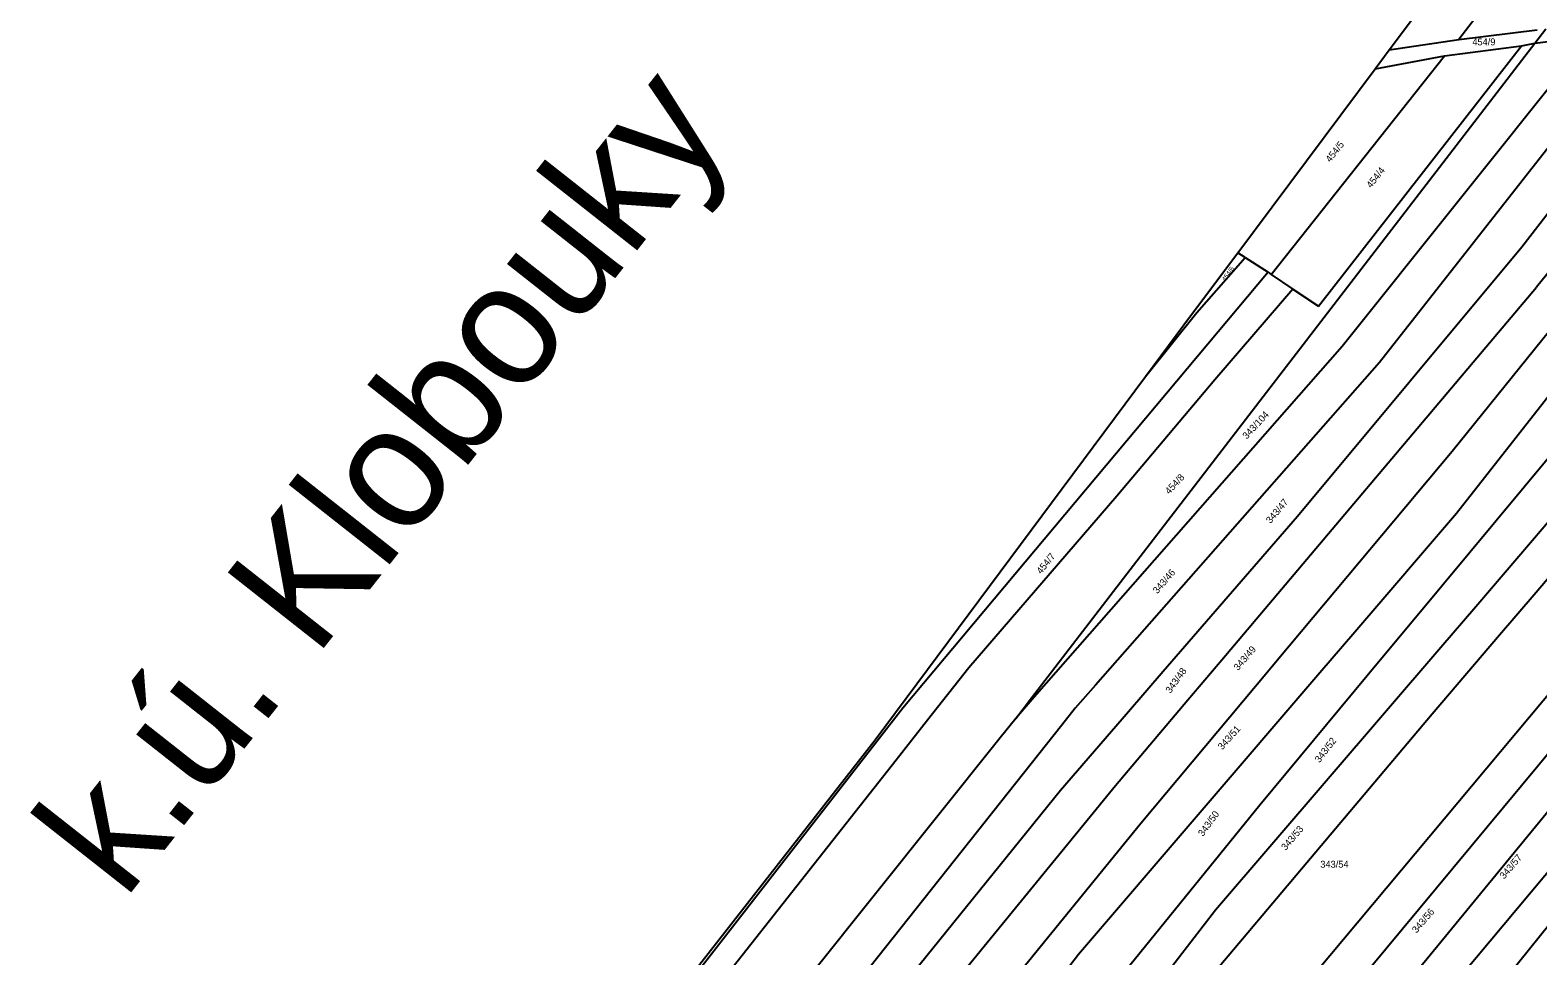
# Model space of a CAD drawing. Extents: x -580630 to -576196, y -1189024 to -1183567.
# Drawn here: x -580495.5 to -580125.3, y -1185848.6 to -1185621.3 of the extents above; entities that cross this region are included whole.
import ezdxf

# ---------------------------------------------------------------- set-up
doc = ezdxf.new("R2010")
doc.units = 0
for name, color, linetype in [('Vrstva 1', 7, 'Continuous'), ('Vrstva 13', 7, 'Continuous'), ('Vrstva 18', 7, 'Continuous'), ('Vrstva 6', 7, 'Continuous'), ('Vrstva 61', 7, 'Continuous')]:
    doc.layers.add(name, color=color, linetype=linetype)

msp = doc.modelspace()

# ---------------------------------------------------------------- linework, layer by layer
at = {"layer": 'Vrstva 1'}
for p, q in [((-580126.09, -1185624.48), (-580123.34, -1185620.94)), ((-580249.66, -1185785.26), (-580126.09, -1185624.48)), ((-580189.56, -1185894.3), (-580077.82, -1185758.25)), ((-580253.54, -1185790.3), (-580249.66, -1185785.26)), ((-580253.54, -1185790.3), (-580257.35, -1185795.07)), ((-580257.35, -1185795.07), (-580303.59, -1185852.97))]:
    msp.add_line(p, q, dxfattribs=at)
at = {"layer": 'Vrstva 13'}
for p, q in [((-580161.82, -1185626.13), (-580139.93, -1185596.8)), ((-580165.31, -1185630.8), (-580161.82, -1185626.13)), ((-580199, -1185675.94), (-580165.31, -1185630.8)), ((-580210.35, -1185691.15), (-580199, -1185675.94)), ((-580221.65, -1185706.34), (-580210.35, -1185691.15)), ((-580288.01, -1185795.54), (-580221.65, -1185706.34)), ((-580358.28, -1185885.39), (-580288.01, -1185795.54))]:
    msp.add_line(p, q, dxfattribs=at)
at = {"layer": 'Vrstva 6'}
for p, q in [((-580040.48, -1185487.18), (-580144.73, -1185623.59)), ((-580044.77, -1185611.67), (-580145.31, -1185740)), ((-580057.93, -1185615), (-580146.37, -1185724.78)), ((-580071.89, -1185617.85), (-580125.68, -1185684.41)), ((-580100.26, -1185621.38), (-580164.23, -1185702.87)), ((-580144.73, -1185623.59), (-580125.5, -1185621.21)), ((-580087, -1185619.79), (-580129.27, -1185674.58)), ((-580179.16, -1185689.04), (-580129.37, -1185625.12)), ((-580112.59, -1185622.86), (-580173.41, -1185698.95)), ((-580161.82, -1185626.13), (-580144.73, -1185623.59)), ((-580148.25, -1185627.63), (-580129.37, -1185625.12)), ((-580129.37, -1185625.12), (-580126.09, -1185624.48)), ((-580126.09, -1185624.48), (-580112.59, -1185622.86)), ((-580190.78, -1185681.29), (-580148.25, -1185627.63)), ((-580165.31, -1185630.8), (-580148.25, -1185627.63)), ((-580209.02, -1185690.65), (-580197.19, -1185677.1)), ((-580197.19, -1185677.1), (-580199, -1185675.94)), ((-580197.19, -1185677.1), (-580191.58, -1185680.71)), ((-580129.27, -1185674.58), (-580184.31, -1185740.71)), ((-580191.58, -1185680.71), (-580281.28, -1185787.81)), ((-580191.58, -1185680.71), (-580190.78, -1185681.29)), ((-580202.96, -1185775.93), (-580125.68, -1185684.41)), ((-580190.78, -1185681.29), (-580185.51, -1185684.93)), ((-580185.51, -1185684.93), (-580204.64, -1185707.18)), ((-580185.51, -1185684.93), (-580179.16, -1185689.04)), ((-580221.65, -1185706.34), (-580209.02, -1185690.65)), ((-580173.41, -1185698.95), (-580249, -1185785.12)), ((-580164.23, -1185702.87), (-580233.94, -1185782.12)), ((-580204.64, -1185707.18), (-580228.67, -1185735.7)), ((-580017.59, -1185710.64), (-580171.19, -1185901.31)), ((-580146.37, -1185724.78), (-580186.35, -1185772.54)), ((-580121.78, -1185725.25), (-580155.77, -1185766.1)), ((-580228.67, -1185735.7), (-580265.04, -1185777.88)), ((-580117.05, -1185735.44), (-580140.59, -1185762.9)), ((-580103.91, -1185733.76), (-580126.26, -1185759.95)), ((-580145.31, -1185740), (-580170.3, -1185769.16)), ((-580184.31, -1185740.71), (-580217.29, -1185778.79)), ((-580174.56, -1185861.14), (-580083.2, -1185751.18)), ((-580059.05, -1185751.68), (-580178.06, -1185893.99)), ((-580126.26, -1185759.95), (-580134.71, -1185769.84)), ((-580211.03, -1185889.9), (-580105.71, -1185763.93)), ((-580155.77, -1185766.1), (-580164.02, -1185776.02)), ((-580140.59, -1185762.9), (-580149.15, -1185772.88)), ((-580170.3, -1185769.16), (-580178.85, -1185779.14)), ((-580134.71, -1185769.84), (-580151.3, -1185789.28)), ((-580149.15, -1185772.88), (-580204.46, -1185837.4)), ((-580186.35, -1185772.54), (-580194.62, -1185782.43)), ((-580211.25, -1185785.75), (-580202.96, -1185775.93)), ((-580164.02, -1185776.02), (-580193.62, -1185811.58)), ((-580265.04, -1185777.88), (-580275.16, -1185790.71)), ((-580178.85, -1185779.14), (-580238.08, -1185848.26)), ((-580217.29, -1185778.79), (-580225.83, -1185788.66)), ((-580233.94, -1185782.12), (-580238.93, -1185787.79)), ((-580194.62, -1185782.43), (-580222.8, -1185816.09)), ((-580281.28, -1185787.81), (-580331.12, -1185851.88)), ((-580249, -1185785.12), (-580253.54, -1185790.3)), ((-580238.93, -1185787.79), (-580242.21, -1185791.93)), ((-580229.01, -1185806.78), (-580211.25, -1185785.75)), ((-580242.21, -1185791.93), (-580289.28, -1185851.33)), ((-580275.16, -1185790.71), (-580282.92, -1185800.56)), ((-580225.83, -1185788.66), (-580242.55, -1185807.97)), ((-580151.3, -1185789.28), (-580210.5, -1185859.48)), ((-580282.92, -1185800.56), (-580332.16, -1185863.02)), ((-580265.99, -1185852.06), (-580229.01, -1185806.78)), ((-580242.55, -1185807.97), (-580288.58, -1185864.9)), ((-580193.62, -1185811.58), (-580260.15, -1185893.74)), ((-580222.8, -1185816.09), (-580261.85, -1185863.97)), ((-580204.46, -1185837.4), (-580250.59, -1185897.1)), ((-580238.08, -1185848.26), (-580268.02, -1185887.2))]:
    msp.add_line(p, q, dxfattribs=at)

# ---------------------------------------------------------------- texts
at = {"layer": 'Vrstva 18'}
for s, p in [('454/9', (-580141.42, -1185625.03)), ('343/54', (-580178.743, -1185826.97))]:
    msp.add_text(s, height=1.7, dxfattribs=at).set_placement(p)
for s, height, rotation, p in [('454/5', 1.7, 51.5662, (-580176.302, -1185653.883)), ('454/4', 1.7, 51.5662, (-580166.273, -1185660.226)), ('454/6', 1.14, 54.83206, (-580202.084, -1185683.068)), ('343/104', 1.7, 47.15443, (-580196.802, -1185721.86)), ('454/8', 1.7, 47.15443, (-580215.83, -1185735.396)), ('343/47', 1.7, 49.73274, (-580190.971, -1185742.578)), ('454/7', 1.7, 51.16513, (-580247.277, -1185754.989)), ('343/46', 1.7, 49.10248, (-580218.763, -1185759.818)), ('343/49', 1.7, 49.21708, (-580198.926, -1185778.683)), ('343/48', 1.7, 54.14451, (-580215.538, -1185784.289)), ('343/51', 1.7, 48.24305, (-580202.821, -1185798.17)), ('343/52', 1.7, 52.19646, (-580178.947, -1185801.32)), ('343/50', 1.7, 54.08722, (-580207.533, -1185819.419)), ('343/53', 1.7, 49.84733, (-580187.227, -1185822.846)), ('343/57', 1.7, 49.61814, (-580133.588, -1185829.878)), ('343/56', 1.7, 49.61814, (-580155.104, -1185843.159))]:
    msp.add_text(s, height=height, rotation=rotation, dxfattribs=at).set_placement(p)
at = {"layer": 'Vrstva 61'}
msp.add_text('k.ú. Klobouky', height=30, rotation=51.7605, dxfattribs=at).set_placement((-580472.399, -1185835.149))

doc.saveas('drawing.dxf')
